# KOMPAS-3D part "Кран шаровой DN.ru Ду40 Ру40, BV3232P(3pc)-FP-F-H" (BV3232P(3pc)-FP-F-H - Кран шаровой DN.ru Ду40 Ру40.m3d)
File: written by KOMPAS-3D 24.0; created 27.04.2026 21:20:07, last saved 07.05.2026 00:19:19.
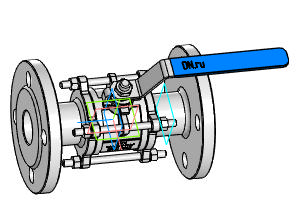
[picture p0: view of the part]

Document properties: Автор: Максим; Полное имя файла: BVxxP(3pc)-FP-F-H - Кран шаровой DN.ru Ду40 Ру40.cdw

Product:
- Body: Тело 1  | qty 1
    Масса: 6.973798
- Part/product: Кран шаровой DN.ru Ду40 Ру40  | designation BV3232P(3pc)-FP-F-H
    Масса: 6.105
    Раздел спецификации: Прочие изделия
    Форматы листов документа: A2
    Примечание: D160-22805

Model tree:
1. Операция без истории:1
2. Эскиз:1  (with: Ребро.Операция без истории:1)
3. Элемент выдавливания:1
     Расстояние 1 = 3
4. Эскиз:2  (with: Грань.Операция без истории:1)
5. Элемент выдавливания:3
     Расстояние 2 = 35
6. Эскиз:3  (with: Грань.Элемент выдавливания:3)
7. Элемент выдавливания:4  (with: Грань.Операция без истории:1)
     Расстояние 1 = 27
8. Эскиз:4  (with: Грань.Операция без истории:1)
9. Элемент выдавливания:5
     Расстояние 1 = 8
10. Фаска:1  (with: Ребро.Элемент выдавливания:5)
     Угол = 45; Длина 1 = 1.6; Длина 2 = 1.6
11. Эскиз:5  (with: Ребро.Элемент выдавливания:1, Ребро.Элемент выдавливания:4)
12. Элемент выдавливания:6
     Расстояние 1 = 10
13. Эскиз:6  (with: Ребро.Элемент выдавливания:6)
14. Элемент выдавливания:7
     Расстояние 1 = 23
15. Фаска:2  (with: Ребро.Элемент выдавливания:7)
     Угол = 45; Длина 1 = 5; Длина 2 = 5
16. Скругление:1  (with: Ребро.Элемент выдавливания:1)
     Радиус = 3
17. Скругление:2  (with: Ребро.Элемент выдавливания:1)
     Радиус = 6
18. Эскиз:7  (with: Ребро.Элемент выдавливания:7)
19. Элемент выдавливания:8
     Расстояние 1 = 24
20. Скругление:3  (with: Ребро.Элемент выдавливания:8)
     Радиус = 7.5
21. Скругление:4  (with: Ребро.Элемент выдавливания:8)
     Радиус = 0.5
22. Эскиз:8  (with: Грань.Операция без истории:1, Ребро.Операция без истории:1)
23. Элемент выдавливания:9  (with: Грань.Операция без истории:1)
     Расстояние 2 = 200
24. Смещенная плоскость:1
     Расстояние = -61
25. Эскиз:9  (with: Ребро.Операция без истории:1)
26. Элемент выдавливания:10
     Расстояние 1 = 21
27. Зеркальный массив:1
28. Экземпляр ( 1 )
29. Экземпляр ( 2 )  (with: Элемент выдавливания:10)
30. Эскиз:10  (with: Грань.Операция без истории:1)
31. Элемент выдавливания:11
     Расстояние 1 = 10
32. Эскиз:11  (with: Грань.Операция без истории:1)
33. Элемент выдавливания:12
     Расстояние 1 = 0.2
34. Эскиз:12  (with: Грань.Операция без истории:1)
35. Элемент выдавливания:13
     Расстояние 1 = 0.2
36. Эскиз:13  (with: Грань.Элемент выдавливания:8, Ребро.Скругление:4, Ребро.Элемент выдавливания:8)
37. Элемент выдавливания:14
     Расстояние 2 = 0.2

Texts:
  BV3232P(3pc)-FP-F-H
  DN40 PN40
